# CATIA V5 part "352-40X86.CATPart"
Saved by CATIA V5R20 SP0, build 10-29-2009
Part number: 352-40X86
Definition: NONE
Nomenclature: 352-40X86
Source: Unknown
Description: 352-40X86
Bounding box of the stored display mesh (mm): x 0 to 86, y -24 to 24, z -24 to 24
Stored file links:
  C:\Users\Utente\Desktop\IO LAVORO\3D X SITO CF\X SITO\PLASTICA\352\352-40X86.CATPart

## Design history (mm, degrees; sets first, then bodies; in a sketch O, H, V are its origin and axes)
Body1 "352-40X86" (main body)
  Solid1: solid without history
